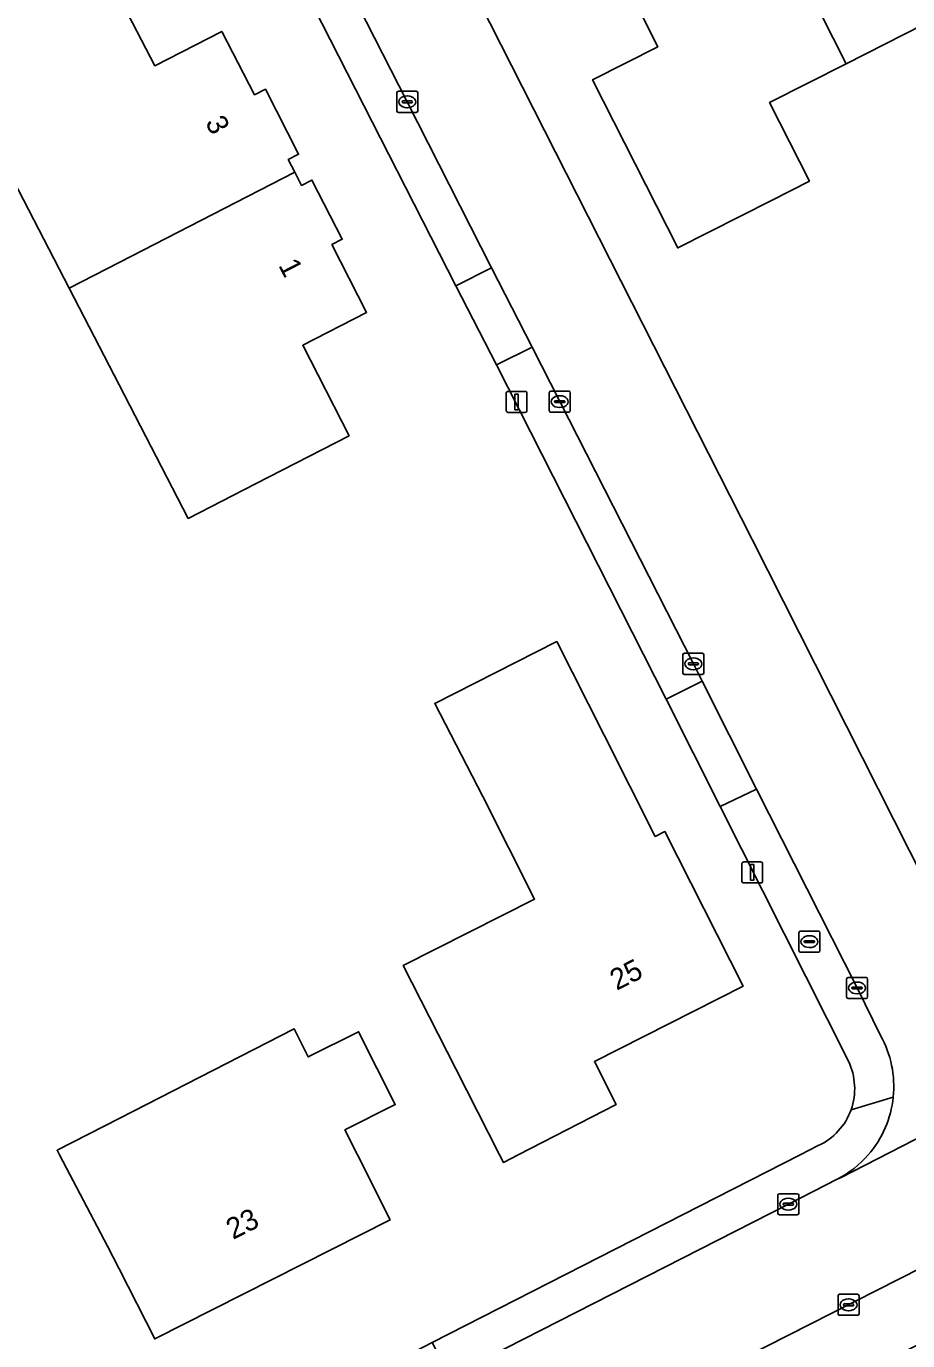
# Model space of a CAD drawing. Extents: x 162722 to 165104, y 384719 to 386284.
# Drawn here: x 163995.6 to 164037.5, y 384991.2 to 385053.7 of the extents above; entities that cross this region are included whole.
import ezdxf

# ---------------------------------------------------------------- set-up
doc = ezdxf.new("R2010")
doc.units = 0
for name, color, linetype in [('IMGEO_Brandkraan', 7, 'Continuous'), ('IMGEO_Erf', 7, 'Continuous'), ('IMGEO_Groenvoorziening', 7, 'Continuous'), ('IMGEO_Kolk', 7, 'Continuous'), ('IMGEO_Lichtmast', 7, 'Continuous'), ('IMGEO_Pand', 7, 'Continuous'), ('IMGEO_Pand_nummerreeks', 7, 'Continuous'), ('IMGEO_Parkeervlak_open', 7, 'Continuous'), ('IMGEO_Rijbaan_lokaal_open', 7, 'Continuous'), ('IMGEO_Voetpad_open', 7, 'Continuous')]:
    doc.layers.add(name, color=color, linetype=linetype)

msp = doc.modelspace()

# ---------------------------------------------------------------- linework, layer by layer
at = {"layer": 'IMGEO_Brandkraan'}
for p, q in [((164032.34, 385009.72), (164032.34, 385010.572)), ((164032.415, 385010.646), (164033.267, 385010.646)), ((164032.828, 385010.426), (164032.853, 385010.426)), ((164033.341, 385010.572), (164033.341, 385009.72)), ((164033.267, 385009.646), (164032.415, 385009.646)), ((164032.599, 385010.14), (164032.599, 385010.152)), ((164033.037, 385010.103), (164032.639, 385010.103)), ((164032.642, 385010.189), (164033.04, 385010.189)), ((164032.851, 385009.866), (164032.826, 385009.866)), ((164033.083, 385010.152), (164033.083, 385010.14))]:
    msp.add_line(p, q, dxfattribs=at)
for points in [[(164032.34, 385009.72), (164032.34, 385010.572)], [(164032.415, 385010.646), (164033.267, 385010.646)], [(164033.341, 385010.572), (164033.341, 385009.72)], [(164033.267, 385009.646), (164032.415, 385009.646)]]:
    msp.add_lwpolyline(points, dxfattribs=at)
for centre, radius, start, end in [((164032.417, 385010.57), 0.0765, 91.55205, 178.44795), ((164032.417, 385010.57), 0.0765, 91.55205, 178.44795), ((164033.265, 385010.57), 0.0765, 1.55205, 88.44795), ((164033.265, 385010.57), 0.0765, 1.55205, 88.44795), ((164032.417, 385009.722), 0.0765, 181.55205, 268.44795), ((164032.417, 385009.722), 0.0765, 181.55205, 268.44795), ((164032.639, 385010.149), 0.0403, 85.87752, 175.75265), ((164032.636, 385010.139), 0.0366, 178.93798, 274.71019), ((164033.04, 385010.146), 0.043, 264.86636, 352.45326), ((164033.044, 385010.151), 0.0386, 1.73085, 96.63898), ((164033.265, 385009.722), 0.0765, 271.55205, 358.44795), ((164033.265, 385009.722), 0.0765, 271.55205, 358.44795)]:
    msp.add_arc(centre, radius, start, end, dxfattribs=at)
for centre, major_axis, ratio, start_param, end_param in [((164032.827, 385010.146), (-0.387, 0.002), 0.722429, 4.712389, 7.853982), ((164032.852, 385010.146), (-0.39, 0.002), 0.717154, 1.570796, 4.712389)]:
    msp.add_ellipse(centre, major_axis=major_axis, ratio=ratio, start_param=start_param, end_param=end_param, dxfattribs=at)
at = {"layer": 'IMGEO_Erf'}
for points in [[(164000, 385055.098), (164001.698, 385051.814), (164004.886, 385053.449), (164006.448, 385050.435), (164006.957, 385050.696), (164008.542, 385047.605), (164008.046, 385047.35), (164008.358, 385046.749), (164008.678, 385046.125), (164009.171, 385046.378), (164010.618, 385043.557), (164010.125, 385043.304), (164011.777, 385040.081), (164008.734, 385038.521), (164010.944, 385034.211), (164006.495, 385031.929), (164003.287, 385030.284), (164000, 385036.633), (163997.619, 385041.233), (163991.825, 385052.424), (163986.101, 385063.481)], [(164017.949, 385037.586), (164016.024, 385041.339), (164005.266, 385062.437)], [(164017.119, 385054.888), (164030.122, 385029.274), (164040.599, 385008.534), (164040.957, 385008.624)], [(164034.695, 385004.457), (164028.601, 385016.574), (164026.02, 385021.678), (164017.949, 385037.586)], [(163986.006, 384976.275), (163994.739, 384980.712), (163997.946, 384982.427), (164000, 384983.471), (164012.117, 384989.629), (164014.89, 384991.078), (164032.397, 385000), (164033.264, 385000.442)]]:
    msp.add_lwpolyline(points, dxfattribs=at)
for points in [[(164032.843, 385046.325), (164031.041, 385045.411), (164026.581, 385043.15), (164022.526, 385051.148), (164025.631, 385052.722), (164023.418, 385057.089), (164030.232, 385060.532), (164037.046, 385063.974), (164039.256, 385059.618), (164042.37, 385061.197), (164044.632, 385056.738), (164046.422, 385053.209), (164040.16, 385050.034), (164038.265, 385053.774), (164034.589, 385051.91), (164030.946, 385050.063)], [(164015.017, 385021.483), (164020.817, 385024.418), (164023.07, 385019.965), (164025.507, 385015.149), (164025.963, 385015.38), (164029.686, 385008.024), (164022.613, 385004.445), (164023.648, 385002.4), (164018.982, 385000), (164018.286, 384999.642), (164018.104, 385000), (164016.015, 385004.097), (164013.513, 385009.006), (164019.769, 385012.173), (164017.302, 385017.046)], [(164008.328, 385006.006), (164009.002, 385004.662), (164011.395, 385005.863), (164013.136, 385002.392), (164010.744, 385001.191), (164011.341, 385000), (164012.89, 384996.911), (164001.699, 384991.247), (164000, 384994.579), (163999.45, 384995.658), (163997.17, 385000), (163997.051, 385000.225), (164000, 385001.737)]]:
    msp.add_lwpolyline(points, close=True, dxfattribs=at)
for centre, start, end in [((164032.006, 385003.153), 340.38305, 25.86931), ((164032.006, 385003.152), 294.89526, 340.4006)]:
    msp.add_arc(centre, 2.988, start, end, dxfattribs=at)
at = {"layer": 'IMGEO_Groenvoorziening'}
msp.add_lwpolyline([(164026.982, 384985.419), (164050.725, 384997.366), (164049.366, 385000), (164049.239, 385000.247), (164048.752, 385000), (164025.477, 384988.187)], close=True, dxfattribs=at)
at = {"layer": 'IMGEO_Kolk'}
for p, q in [((164013.21, 385049.672), (164013.21, 385050.524)), ((164013.285, 385050.598), (164014.137, 385050.598)), ((164013.698, 385050.378), (164013.723, 385050.378)), ((164014.211, 385050.524), (164014.211, 385049.672)), ((164013.469, 385050.092), (164013.469, 385050.104)), ((164013.907, 385050.055), (164013.509, 385050.055)), ((164013.512, 385050.141), (164013.91, 385050.141)), ((164013.721, 385049.818), (164013.696, 385049.818)), ((164013.953, 385050.104), (164013.953, 385050.092)), ((164014.137, 385049.598), (164013.285, 385049.598)), ((164020.461, 385035.41), (164020.461, 385036.262)), ((164020.536, 385036.336), (164021.388, 385036.336)), ((164020.763, 385035.879), (164021.161, 385035.879)), ((164020.949, 385036.116), (164020.974, 385036.116)), ((164021.462, 385036.262), (164021.462, 385035.41)), ((164021.388, 385035.336), (164020.536, 385035.336)), ((164020.72, 385035.83), (164020.72, 385035.842)), ((164021.158, 385035.793), (164020.76, 385035.793)), ((164020.972, 385035.556), (164020.947, 385035.556)), ((164021.204, 385035.842), (164021.204, 385035.83)), ((164026.819, 385022.937), (164026.819, 385023.789)), ((164026.894, 385023.863), (164027.746, 385023.863)), ((164027.078, 385023.357), (164027.078, 385023.369)), ((164027.121, 385023.406), (164027.519, 385023.406)), ((164027.307, 385023.643), (164027.332, 385023.643)), ((164027.562, 385023.369), (164027.562, 385023.357)), ((164027.82, 385023.789), (164027.82, 385022.937)), ((164027.746, 385022.863), (164026.894, 385022.863)), ((164027.516, 385023.32), (164027.118, 385023.32)), ((164027.33, 385023.083), (164027.305, 385023.083)), ((164034.608, 385007.517), (164034.608, 385008.369)), ((164034.683, 385008.443), (164035.535, 385008.443)), ((164035.609, 385008.369), (164035.609, 385007.517)), ((164034.867, 385007.937), (164034.867, 385007.949)), ((164035.305, 385007.9), (164034.907, 385007.9)), ((164034.91, 385007.986), (164035.308, 385007.986)), ((164035.096, 385008.223), (164035.121, 385008.223)), ((164035.351, 385007.949), (164035.351, 385007.937)), ((164035.535, 385007.443), (164034.683, 385007.443)), ((164035.119, 385007.663), (164035.094, 385007.663)), ((164031.338, 384997.231), (164031.338, 384998.083)), ((164031.413, 384998.157), (164032.265, 384998.157)), ((164031.826, 384997.937), (164031.851, 384997.937)), ((164032.339, 384998.083), (164032.339, 384997.231)), ((164032.265, 384997.157), (164031.413, 384997.157)), ((164031.597, 384997.651), (164031.597, 384997.663)), ((164032.035, 384997.614), (164031.637, 384997.614)), ((164031.64, 384997.7), (164032.038, 384997.7)), ((164031.849, 384997.377), (164031.824, 384997.377)), ((164032.081, 384997.663), (164032.081, 384997.651)), ((164034.279, 384993.37), (164035.131, 384993.37)), ((164034.204, 384992.444), (164034.204, 384993.296)), ((164034.463, 384992.864), (164034.463, 384992.876)), ((164034.901, 384992.827), (164034.503, 384992.827)), ((164034.506, 384992.913), (164034.904, 384992.913)), ((164034.692, 384993.15), (164034.717, 384993.15)), ((164034.947, 384992.876), (164034.947, 384992.864)), ((164035.205, 384993.296), (164035.205, 384992.444)), ((164035.131, 384992.37), (164034.279, 384992.37)), ((164034.715, 384992.59), (164034.69, 384992.59))]:
    msp.add_line(p, q, dxfattribs=at)
for points in [[(164013.21, 385049.672), (164013.21, 385050.524)], [(164013.285, 385050.598), (164014.137, 385050.598)], [(164014.211, 385050.524), (164014.211, 385049.672)], [(164014.137, 385049.598), (164013.285, 385049.598)], [(164020.461, 385035.41), (164020.461, 385036.262)], [(164020.536, 385036.336), (164021.388, 385036.336)], [(164021.462, 385036.262), (164021.462, 385035.41)], [(164021.388, 385035.336), (164020.536, 385035.336)], [(164026.819, 385022.937), (164026.819, 385023.789)], [(164026.894, 385023.863), (164027.746, 385023.863)], [(164027.82, 385023.789), (164027.82, 385022.937)], [(164027.746, 385022.863), (164026.894, 385022.863)], [(164034.608, 385007.517), (164034.608, 385008.369)], [(164034.683, 385008.443), (164035.535, 385008.443)], [(164035.609, 385008.369), (164035.609, 385007.517)], [(164035.535, 385007.443), (164034.683, 385007.443)], [(164031.338, 384997.231), (164031.338, 384998.083)], [(164031.413, 384998.157), (164032.265, 384998.157)], [(164032.339, 384998.083), (164032.339, 384997.231)], [(164032.265, 384997.157), (164031.413, 384997.157)], [(164034.279, 384993.37), (164035.131, 384993.37)], [(164034.204, 384992.444), (164034.204, 384993.296)], [(164035.205, 384993.296), (164035.205, 384992.444)], [(164035.131, 384992.37), (164034.279, 384992.37)]]:
    msp.add_lwpolyline(points, dxfattribs=at)
for centre, radius, start, end in [((164013.287, 385050.522), 0.0765, 91.55205, 178.44795), ((164013.287, 385050.522), 0.0765, 91.55205, 178.44795), ((164014.135, 385050.522), 0.0765, 1.55205, 88.44795), ((164014.135, 385050.522), 0.0765, 1.55205, 88.44795), ((164013.287, 385049.674), 0.0765, 181.55205, 268.44795), ((164013.287, 385049.674), 0.0765, 181.55205, 268.44795), ((164013.509, 385050.101), 0.0403, 85.87752, 175.75265), ((164013.506, 385050.091), 0.0366, 178.93798, 274.71019), ((164013.91, 385050.098), 0.043, 264.86636, 352.45326), ((164013.914, 385050.103), 0.0386, 1.73085, 96.63898), ((164014.135, 385049.674), 0.0765, 271.55205, 358.44795), ((164014.135, 385049.674), 0.0765, 271.55205, 358.44795), ((164020.538, 385036.26), 0.0765, 91.55205, 178.44795), ((164020.538, 385036.26), 0.0765, 91.55205, 178.44795), ((164020.76, 385035.839), 0.0403, 85.87752, 175.75265), ((164021.165, 385035.841), 0.0386, 1.73085, 96.63898), ((164021.386, 385036.26), 0.0765, 1.55205, 88.44795), ((164021.386, 385036.26), 0.0765, 1.55205, 88.44795), ((164020.538, 385035.412), 0.0765, 181.55205, 268.44795), ((164020.538, 385035.412), 0.0765, 181.55205, 268.44795), ((164020.757, 385035.829), 0.0366, 178.93798, 274.71019), ((164021.161, 385035.836), 0.043, 264.86636, 352.45326), ((164021.386, 385035.412), 0.0765, 271.55205, 358.44795), ((164021.386, 385035.412), 0.0765, 271.55205, 358.44795), ((164026.896, 385023.787), 0.0765, 91.55205, 178.44795), ((164026.896, 385023.787), 0.0765, 91.55205, 178.44795), ((164027.118, 385023.366), 0.0403, 85.87752, 175.75265), ((164027.115, 385023.356), 0.0366, 178.93798, 274.71019), ((164027.519, 385023.363), 0.043, 264.86636, 352.45326), ((164027.523, 385023.368), 0.0386, 1.73085, 96.63898), ((164027.744, 385023.787), 0.0765, 1.55205, 88.44795), ((164027.744, 385023.787), 0.0765, 1.55205, 88.44795), ((164026.896, 385022.939), 0.0765, 181.55205, 268.44795), ((164026.896, 385022.939), 0.0765, 181.55205, 268.44795), ((164027.744, 385022.939), 0.0765, 271.55205, 358.44795), ((164027.744, 385022.939), 0.0765, 271.55205, 358.44795), ((164034.685, 385008.367), 0.0765, 91.55205, 178.44795), ((164034.685, 385008.367), 0.0765, 91.55205, 178.44795), ((164035.533, 385008.367), 0.0765, 1.55205, 88.44795), ((164035.533, 385008.367), 0.0765, 1.55205, 88.44795), ((164034.907, 385007.946), 0.0403, 85.87752, 175.75265), ((164034.904, 385007.936), 0.0366, 178.93798, 274.71019), ((164035.308, 385007.943), 0.043, 264.86636, 352.45326), ((164035.312, 385007.948), 0.0386, 1.73085, 96.63898), ((164034.685, 385007.519), 0.0765, 181.55205, 268.44795), ((164034.685, 385007.519), 0.0765, 181.55205, 268.44795), ((164035.533, 385007.519), 0.0765, 271.55205, 358.44795), ((164035.533, 385007.519), 0.0765, 271.55205, 358.44795), ((164031.415, 384998.081), 0.0765, 91.55205, 178.44795), ((164031.415, 384998.081), 0.0765, 91.55205, 178.44795), ((164032.263, 384998.081), 0.0765, 1.55205, 88.44795), ((164032.263, 384998.081), 0.0765, 1.55205, 88.44795), ((164031.415, 384997.233), 0.0765, 181.55205, 268.44795), ((164031.415, 384997.233), 0.0765, 181.55205, 268.44795), ((164031.637, 384997.66), 0.0403, 85.87752, 175.75265), ((164031.634, 384997.65), 0.0366, 178.93798, 274.71019), ((164032.038, 384997.657), 0.043, 264.86636, 352.45326), ((164032.042, 384997.662), 0.0386, 1.73085, 96.63898), ((164032.263, 384997.233), 0.0765, 271.55205, 358.44795), ((164032.263, 384997.233), 0.0765, 271.55205, 358.44795), ((164034.281, 384993.294), 0.0765, 91.55205, 178.44795), ((164034.281, 384993.294), 0.0765, 91.55205, 178.44795), ((164035.129, 384993.294), 0.0765, 1.55205, 88.44795), ((164035.129, 384993.294), 0.0765, 1.55205, 88.44795), ((164034.503, 384992.873), 0.0403, 85.87752, 175.75265), ((164034.5, 384992.863), 0.0366, 178.93798, 274.71019), ((164034.904, 384992.87), 0.043, 264.86636, 352.45326), ((164034.908, 384992.875), 0.0386, 1.73085, 96.63898), ((164034.281, 384992.446), 0.0765, 181.55205, 268.44795), ((164034.281, 384992.446), 0.0765, 181.55205, 268.44795), ((164035.129, 384992.446), 0.0765, 271.55205, 358.44795), ((164035.129, 384992.446), 0.0765, 271.55205, 358.44795)]:
    msp.add_arc(centre, radius, start, end, dxfattribs=at)
for centre, major_axis, ratio, start_param, end_param in [((164013.697, 385050.098), (-0.387, 0.002), 0.722429, 4.712389, 7.853982), ((164013.722, 385050.098), (-0.39, 0.002), 0.717154, 1.570796, 4.712389), ((164020.948, 385035.836), (-0.387, 0.002), 0.722429, 4.712389, 7.853982), ((164020.973, 385035.836), (-0.39, 0.002), 0.717154, 1.570796, 4.712389), ((164027.306, 385023.363), (-0.387, 0.002), 0.722429, 4.712389, 7.853982), ((164027.331, 385023.363), (-0.39, 0.002), 0.717154, 1.570796, 4.712389), ((164035.095, 385007.943), (-0.387, 0.002), 0.722429, 4.712389, 7.853982), ((164035.12, 385007.943), (-0.39, 0.002), 0.717154, 1.570796, 4.712389), ((164031.825, 384997.657), (-0.387, 0.002), 0.722429, 4.712389, 7.853982), ((164031.85, 384997.657), (-0.39, 0.002), 0.717154, 1.570796, 4.712389), ((164034.691, 384992.87), (-0.387, 0.002), 0.722429, 4.712389, 7.853982), ((164034.716, 384992.87), (-0.39, 0.002), 0.717154, 1.570796, 4.712389)]:
    msp.add_ellipse(centre, major_axis=major_axis, ratio=ratio, start_param=start_param, end_param=end_param, dxfattribs=at)
at = {"layer": 'IMGEO_Lichtmast'}
for p, q in [((164018.414, 385035.424), (164018.414, 385036.224)), ((164018.414, 385036.224), (164018.414, 385035.424)), ((164018.514, 385036.324), (164019.304, 385036.324)), ((164019.304, 385036.324), (164018.514, 385036.324)), ((164019.404, 385036.224), (164019.404, 385035.424)), ((164019.404, 385035.424), (164019.404, 385036.224)), ((164019.304, 385035.324), (164018.514, 385035.324)), ((164018.514, 385035.324), (164019.304, 385035.324)), ((164029.626, 385013.039), (164029.626, 385013.839)), ((164029.626, 385013.839), (164029.626, 385013.039)), ((164029.726, 385013.939), (164030.516, 385013.939)), ((164030.516, 385013.939), (164029.726, 385013.939)), ((164030.616, 385013.839), (164030.616, 385013.039)), ((164030.616, 385013.039), (164030.616, 385013.839)), ((164030.516, 385012.939), (164029.726, 385012.939)), ((164029.726, 385012.939), (164030.516, 385012.939))]:
    msp.add_line(p, q, dxfattribs=at)
for points in [[(164018.834, 385036.199), (164018.984, 385036.199), (164018.984, 385035.449), (164018.834, 385035.449), (164018.834, 385036.199)], [(164030.046, 385013.814), (164030.196, 385013.814), (164030.196, 385013.064), (164030.046, 385013.064), (164030.046, 385013.814)]]:
    msp.add_lwpolyline(points, dxfattribs=at)
for centre, start, end in [((164018.514, 385036.224), 90, 180), ((164018.514, 385036.224), 90, 180), ((164019.304, 385036.224), 0, 90), ((164019.304, 385036.224), 360, 90), ((164018.514, 385035.424), 180, 270), ((164018.514, 385035.424), 180, 270), ((164019.304, 385035.424), 270, 0), ((164019.304, 385035.424), 270, 0), ((164029.726, 385013.839), 90, 180), ((164029.726, 385013.839), 90, 180), ((164030.516, 385013.839), 0, 90), ((164030.516, 385013.839), 360, 90), ((164029.726, 385013.039), 180, 270), ((164029.726, 385013.039), 180, 270), ((164030.516, 385013.039), 270, 0), ((164030.516, 385013.039), 270, 0)]:
    msp.add_arc(centre, 0.1, start, end, dxfattribs=at)
at = {"layer": 'IMGEO_Pand'}
for points in [[(164034.589, 385051.91), (164038.265, 385053.774), (164040.16, 385050.034), (164046.422, 385053.209), (164044.632, 385056.738), (164042.37, 385061.197), (164039.256, 385059.618), (164037.046, 385063.974), (164030.232, 385060.532)], [(164030.232, 385060.532), (164023.418, 385057.089), (164025.631, 385052.722), (164022.526, 385051.148), (164026.581, 385043.15), (164031.041, 385045.411), (164032.843, 385046.325), (164030.946, 385050.063), (164034.589, 385051.91)], [(164001.698, 385051.814), (164000, 385055.098), (163999.373, 385056.311), (163991.825, 385052.424), (163997.619, 385041.233), (164000, 385042.456), (164008.358, 385046.749), (164008.046, 385047.35), (164008.542, 385047.605), (164006.957, 385050.696), (164006.448, 385050.435), (164004.886, 385053.449)], [(164008.734, 385038.521), (164011.777, 385040.081), (164010.125, 385043.304), (164010.618, 385043.557), (164009.171, 385046.378), (164008.678, 385046.125), (164008.358, 385046.749), (164000, 385042.456), (163997.619, 385041.233), (164000, 385036.633), (164003.287, 385030.284), (164006.495, 385031.929), (164010.944, 385034.211)], [(164025.963, 385015.38), (164025.507, 385015.149), (164023.07, 385019.965), (164020.817, 385024.418), (164015.017, 385021.483), (164017.302, 385017.046), (164019.769, 385012.173), (164013.513, 385009.006), (164016.015, 385004.097), (164018.104, 385000), (164018.286, 384999.642), (164018.982, 385000), (164023.648, 385002.4), (164022.613, 385004.445), (164029.686, 385008.024)], [(164011.341, 385000), (164010.744, 385001.191), (164013.136, 385002.392), (164011.395, 385005.863), (164009.002, 385004.662), (164008.328, 385006.006), (164000, 385001.737), (163997.051, 385000.225), (163997.17, 385000), (163999.45, 384995.658), (164000, 384994.579), (164001.699, 384991.247), (164012.89, 384996.911)]]:
    msp.add_lwpolyline(points, close=True, dxfattribs=at)
at = {"layer": 'IMGEO_Parkeervlak_open'}
for points in [[(164030.324, 385017.406), (164028.601, 385016.574), (164034.695, 385004.457)], [(164036.222, 385005.682), (164035.109, 385007.943), (164030.324, 385017.406)], [(164034.821, 385002.15), (164036.828, 385002.748)], [(164036.828, 385002.748), (164034.821, 385002.15)], [(164033.264, 385000.442), (164032.397, 385000), (164014.89, 384991.078), (164015.73, 384989.449), (164016.722, 384989.956), (164031.839, 384997.657)], [(164031.839, 384997.657), (164034.19, 384998.857)]]:
    msp.add_lwpolyline(points, dxfattribs=at)
for centre, radius, start, end in [((164031.878, 385003.255), 4.976, 354.14934, 29.19065), ((164032.006, 385003.153), 2.988, 340.38305, 25.86931), ((164031.896, 385003.254), 4.958, 318.98755, 354.14805), ((164032.006, 385003.152), 2.988, 294.89526, 340.4006), ((164031.881, 385003.267), 4.978, 297.63161, 318.97953)]:
    msp.add_arc(centre, radius, start, end, dxfattribs=at)
at = {"layer": 'IMGEO_Rijbaan_lokaal_open'}
for points in [[(164010.195, 385056.975), (164013.711, 385050.098), (164017.722, 385042.203), (164019.645, 385038.43), (164020.962, 385035.836), (164027.32, 385023.363), (164027.737, 385022.536), (164030.324, 385017.406), (164035.109, 385007.943), (164036.222, 385005.682)], [(164030.122, 385029.274), (164017.119, 385054.888)], [(164101.609, 385033.009), (164096.471, 385030.405), (164088.372, 385026.349), (164082.061, 385023.117), (164081.011, 385022.579), (164066.906, 385015.461), (164065.538, 385014.795), (164058.234, 385011.087), (164052.18, 385007.948), (164046.901, 385005.343), (164046.648, 385005.238), (164034.319, 384998.907), (164034.19, 384998.857), (164031.839, 384997.657), (164016.722, 384989.956), (164015.73, 384989.449), (164012.885, 384988.012), (164002.685, 384982.806), (164000, 384981.448), (163998.758, 384980.82), (163995.493, 384979.191), (163988.741, 384975.747), (163986.456, 384974.572)], [(164040.957, 385008.624), (164040.599, 385008.534), (164030.122, 385029.274)], [(163989.052, 384969.703), (163993.208, 384971.822), (163999.171, 384974.857), (164000, 384975.271), (164000.843, 384975.693), (164016.445, 384983.616), (164019.048, 384984.967), (164025.477, 384988.187), (164048.752, 385000), (164049.239, 385000.247), (164053.614, 385002.474), (164054.784, 385003.095), (164069.482, 385010.558), (164077.864, 385014.778), (164083.036, 385017.376), (164084.605, 385018.186), (164093.91, 385022.896), (164098.211, 385025.06), (164100.766, 385026.367), (164104.574, 385028.285)], [(164034.19, 384998.857), (164034.319, 384998.907), (164046.648, 385005.238)]]:
    msp.add_lwpolyline(points, dxfattribs=at)
for centre, radius, start, end in [((164031.878, 385003.255), 4.976, 354.14934, 29.19065), ((164031.896, 385003.254), 4.958, 318.98755, 354.14805), ((164031.881, 385003.267), 4.978, 297.63161, 318.97953)]:
    msp.add_arc(centre, radius, start, end, dxfattribs=at)
at = {"layer": 'IMGEO_Voetpad_open'}
msp.add_lwpolyline([(164041.383, 385078.606), (164040.517, 385080.323), (164010.614, 385065.161), (164005.266, 385062.437), (164016.024, 385041.339), (164017.722, 385042.203), (164013.711, 385050.098), (164010.195, 385056.975), (164009.757, 385056.761), (164009.584, 385057.091)], dxfattribs=at)
for points in [[(164019.645, 385038.43), (164017.722, 385042.203), (164016.024, 385041.339), (164017.949, 385037.586)], [(164026.02, 385021.678), (164027.737, 385022.536), (164027.32, 385023.363), (164020.962, 385035.836), (164019.645, 385038.43), (164017.949, 385037.586)], [(164028.601, 385016.574), (164030.324, 385017.406), (164027.737, 385022.536), (164026.02, 385021.678)]]:
    msp.add_lwpolyline(points, close=True, dxfattribs=at)

# ---------------------------------------------------------------- texts
at = {"layer": 'IMGEO_Pand_nummerreeks'}
for s, rotation, p in [('3', 297.15226, (164004.079, 385049.119)), ('1', 297.15226, (164007.563, 385042.326)), ('25', 26.83734, (164023.675, 385007.807)), ('23', 26.84307, (164005.419, 384995.954))]:
    msp.add_text(s, height=1, rotation=rotation, dxfattribs=at).set_placement(p)

doc.saveas('drawing.dxf')
